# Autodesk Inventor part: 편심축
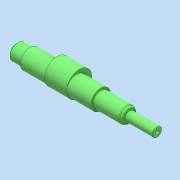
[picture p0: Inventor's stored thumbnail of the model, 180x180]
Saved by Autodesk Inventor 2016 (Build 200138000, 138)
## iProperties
Created: 2024-09
Part Number: 편심축
Material: 일반
Document SubType Name: Modeling
Designer: pc-7
Density: 1 g/cm^3
Appearance: 기본값
Author: jhkim
Sending System: Autodesk Inventor 2025
Preprocessor: ST-DEVELOPER v20
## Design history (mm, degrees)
node "편심축1"
node "솔리드2"
node "솔리드1"
